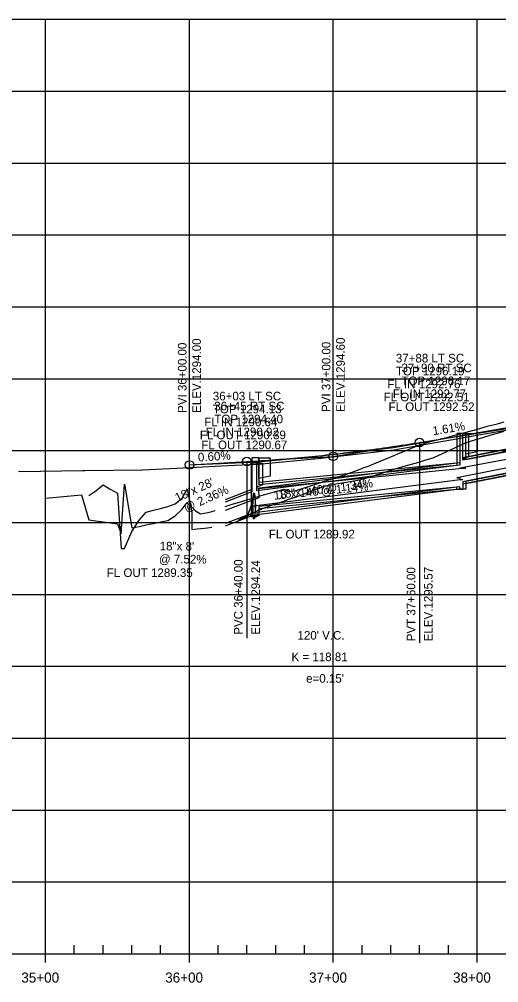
# Model space of a CAD drawing. Extents: x 670877 to 686811, y 705985 to 708501.
# Drawn here: x 684955 to 685288, y 707018 to 707688 of the extents above; entities that cross this region are included whole.
import ezdxf

# ---------------------------------------------------------------- set-up
doc = ezdxf.new("R2010")
doc.units = 0
for name, color, linetype in [('30', 7, 'Continuous'), ('37', 7, 'Continuous'), ('DRAINAGE_HGL LEFT', 7, 'Continuous'), ('DRAINAGE_HGL RIGHT', 7, 'Continuous'), ('Profile Drainage Annot Left', 7, 'Continuous'), ('Profile Drainage Annot Right', 7, 'Continuous'), ('R_Drainage Extensions_LEFT', 7, 'Continuous'), ('R_Drainage LEFT', 7, 'Continuous'), ('R_Drainage RIGHT', 7, 'Continuous'), ('R_Exist Surface', 7, 'Continuous'), ('R_Profile Work Left', 7, 'Continuous'), ('R_Profile Work Right', 7, 'Continuous'), ('R_Vert Alg', 7, 'Continuous'), ('R_Vert Alg Annot', 7, 'Continuous')]:
    doc.layers.add(name, color=color, linetype=linetype)

msp = doc.modelspace()

# ---------------------------------------------------------------- linework, layer by layer
at = {"layer": '37'}
for p, q in [((684473.03, 707688.43), (686573.03, 707688.43)), ((684973.03, 707038.43), (684973.03, 707688.43)), ((685073.03, 707038.43), (685073.03, 707688.43)), ((685173.03, 707038.43), (685173.03, 707688.43)), ((685273.03, 707038.43), (685273.03, 707688.43)), ((684473.03, 707638.43), (686573.03, 707638.43)), ((684473.03, 707588.43), (686573.03, 707588.43)), ((684473.03, 707538.43), (686573.03, 707538.43)), ((684473.03, 707488.43), (686573.03, 707488.43)), ((684473.03, 707438.43), (686573.03, 707438.43)), ((684473.03, 707388.43), (686573.03, 707388.43)), ((684473.03, 707338.43), (686573.03, 707338.43)), ((684473.03, 707288.43), (686573.03, 707288.43)), ((684473.03, 707238.43), (686573.03, 707238.43)), ((684473.03, 707188.43), (686573.03, 707188.43)), ((684473.03, 707138.43), (686573.03, 707138.43)), ((684473.03, 707088.43), (686573.03, 707088.43)), ((684993.03, 707038.43), (684993.03, 707044.43)), ((685013.03, 707038.43), (685013.03, 707044.43)), ((685033.03, 707038.43), (685033.03, 707044.43)), ((685053.03, 707038.43), (685053.03, 707044.43)), ((685093.03, 707038.43), (685093.03, 707044.43)), ((685113.03, 707038.43), (685113.03, 707044.43)), ((685133.03, 707038.43), (685133.03, 707044.43)), ((685153.03, 707038.43), (685153.03, 707044.43)), ((685193.03, 707038.43), (685193.03, 707044.43)), ((685213.03, 707038.43), (685213.03, 707044.43)), ((685233.03, 707038.43), (685233.03, 707044.43)), ((685253.03, 707038.43), (685253.03, 707044.43)), ((684473.03, 707038.43), (686573.03, 707038.43)), ((684973.03, 707032.43), (684973.03, 707038.43)), ((685073.03, 707032.43), (685073.03, 707038.43)), ((685173.03, 707032.43), (685173.03, 707038.43)), ((685273.03, 707032.43), (685273.03, 707038.43))]:
    msp.add_line(p, q, dxfattribs=at)
at = {"layer": 'DRAINAGE_HGL LEFT'}
for points in [[(685548.38, 707441), (685550.38, 707441), (685550.38, 707441), (685546.6, 707441), (685489.4, 707424), (685487.48, 707424), (685487.48, 707421.93), (685485.57, 707421.93), (685407.03, 707399.93), (685405.03, 707399.93), (685405.03, 707398.05), (685403.03, 707398.05), (685258.95, 707369.45), (685260.95, 707369.45), (685260.95, 707368.25), (685262.95, 707368.25), (685115.94, 707349.55), (685117.94, 707349.55)], [(685073.03, 707378.43), (685078.06, 707378.67), (685094.93, 707379.57), (685119.65, 707380.63), (685120.68, 707380.71), (685164.73, 707384.85), (685166.3, 707385.04), (685212.92, 707390.43), (685214.75, 707390.63), (685262.18, 707399.02), (685262.73, 707399.12), (685263.31, 707399.22), (685310, 707407.29)]]:
    msp.add_lwpolyline(points, dxfattribs=at)
at = {"layer": 'DRAINAGE_HGL RIGHT'}
msp.add_lwpolyline([(685545.7, 707448.17), (685547.73, 707448.17), (685547.73, 707448.17), (685547.73, 707448.17), (685489.71, 707427.57), (685487.73, 707427.57), (685487.73, 707427.18), (685485.75, 707427.18), (685403.03, 707404.88), (685405.03, 707404.88), (685405.03, 707403.45), (685407.03, 707403.45), (685261.02, 707376.21), (685263.02, 707376.21), (685263.02, 707376.21), (685265.02, 707376.21), (685120.97, 707361.92), (685121.24, 707355.66), (685097.92, 707346.66)], dxfattribs=at)
at = {"layer": 'R_Drainage Extensions_LEFT'}
for points in [[(685262.95, 707400.33), (685266.95, 707400.33), (685266.94, 707384.2), (685262.94, 707382.53), (685262.95, 707400.33)], [(685119.94, 707379.63), (685123.94, 707379.63), (685123.94, 707364.63), (685119.94, 707362.96), (685119.94, 707379.63)]]:
    msp.add_lwpolyline(points, dxfattribs=at)
at = {"layer": 'R_Drainage LEFT'}
for points in [[(685403.03, 707411.3), (685262.95, 707383.49)], [(685403.03, 707409.63), (685262.95, 707381.82)], [(685262.95, 707400.33), (685258.95, 707400.33)], [(685258.95, 707400.33), (685258.95, 707378.02)], [(685262.95, 707381.82), (685262.95, 707400.33)], [(685403.03, 707394.63), (685262.95, 707366.82)], [(685403.03, 707392.96), (685262.95, 707365.16)], [(685119.94, 707379.63), (685115.94, 707379.63)], [(685115.94, 707379.63), (685115.94, 707344.83)], [(685258.95, 707379.69), (685119.94, 707362)], [(685119.94, 707360.34), (685119.94, 707379.63)], [(685258.95, 707378.02), (685119.94, 707360.34)], [(685262.95, 707366.82), (685262.95, 707361.35)], [(685258.95, 707363.02), (685119.94, 707345.34)], [(685258.95, 707361.35), (685119.94, 707343.67)], [(685258.95, 707361.35), (685258.95, 707363.02)], [(685262.95, 707361.35), (685258.95, 707361.35)], [(685115.94, 707342.33), (685115.94, 707344.83)], [(685119.94, 707345.34), (685119.94, 707342.33)], [(685119.94, 707342.33), (685115.94, 707342.33)]]:
    msp.add_lwpolyline(points, dxfattribs=at)
for major_axis in [(0, 9.17), (0, 7.5)]:
    msp.add_ellipse((685117.94, 707349.83), major_axis=major_axis, ratio=0.1, dxfattribs=at)
at = {"layer": 'R_Drainage RIGHT'}
for points in [[(685403.03, 707410.32), (685265.02, 707383.57)], [(685403.03, 707408.65), (685265.02, 707381.9)], [(685265.02, 707400.33), (685261.02, 707400.33)], [(685261.02, 707400.33), (685261.02, 707378.24)], [(685265.02, 707381.9), (685265.02, 707400.33)], [(685265.02, 707400.33), (685273.02, 707400.33), (685273.02, 707387.58), (685265.02, 707385.91), (685265.02, 707400.33)], [(685403.03, 707393.65), (685265.02, 707366.9)], [(685403.03, 707391.99), (685265.02, 707365.24)], [(685121.24, 707383.43), (685116.36, 707383.43)], [(685116.36, 707383.43), (685116.36, 707359.75)], [(685121.24, 707383.43), (685129.24, 707383.43), (685129.24, 707370.68), (685121.24, 707369.01), (685121.24, 707383.43)], [(685121.24, 707383.43), (685121.24, 707364.56)], [(685261.02, 707379.9), (685121.24, 707366.23)], [(685261.02, 707378.24), (685121.24, 707364.56)], [(685265.02, 707366.9), (685265.02, 707361.57)], [(685116.36, 707361.41), (685097.92, 707354.3)], [(685116.36, 707359.75), (685097.92, 707352.63)], [(685261.02, 707363.24), (685121.24, 707349.56)], [(685261.02, 707361.57), (685121.24, 707347.9)], [(685261.02, 707361.57), (685261.02, 707363.24)], [(685265.02, 707361.57), (685261.02, 707361.57)], [(685116.36, 707344.75), (685097.92, 707337.63)], [(685116.36, 707343.08), (685116.36, 707344.75)], [(685121.24, 707349.56), (685121.24, 707343.08)], [(685116.36, 707343.08), (685097.92, 707335.96)], [(685121.24, 707343.08), (685116.36, 707343.08)]]:
    msp.add_lwpolyline(points, dxfattribs=at)
at = {"layer": 'R_Exist Surface'}
msp.add_lwpolyline([(684954.35, 707374.02), (684954.94, 707373.95), (684998.66, 707374.54), (685000.29, 707374.63), (685039.92, 707375.15), (685040.51, 707375.16), (685078.15, 707377), (685095.01, 707377.9), (685119.75, 707378.97), (685120.82, 707379.04), (685164.91, 707383.19), (685166.5, 707383.38), (685213.11, 707388.77), (685214.99, 707388.98), (685262.47, 707397.38), (685263.02, 707397.47), (685263.59, 707397.57), (685310.24, 707405.64)], dxfattribs=at)
at = {"layer": 'R_Profile Work Left'}
for points in [[(685116.64, 707352.01), (685113.34, 707343.47), (685107.04, 707339.8), (685112.07, 707342.39), (685117.1, 707344.98), (685121.37, 707347.17), (685122.13, 707347.52), (685127.15, 707349.3), (685132.17, 707351.07), (685137.18, 707352.85), (685137.98, 707353.13), (685142.2, 707354.62), (685147.22, 707356.39), (685152.24, 707358.21), (685157.26, 707360.11), (685162.28, 707362.02), (685166.24, 707363.52), (685167.29, 707363.9), (685172.3, 707364.78), (685177.3, 707365.67), (685182.31, 707366.55), (685187.31, 707367.44), (685192.32, 707368.32), (685192.45, 707368.34), (685197.33, 707369.74), (685202.34, 707371.38), (685207.35, 707373.02), (685212.36, 707374.66), (685215.32, 707375.63), (685217.38, 707376.22), (685222.39, 707377.65), (685227.39, 707379.08), (685232.4, 707380.5), (685237.41, 707381.93), (685242.42, 707383.46), (685247.28, 707385.71), (685247.44, 707385.78), (685252.46, 707388.11), (685257.48, 707390.43), (685259.9, 707391.55), (685260.34, 707391.76), (685260.49, 707391.83), (685261.5, 707392.29), (685262.06, 707392.55), (685263.03, 707393.01), (685263.34, 707393.16), (685267.03, 707394.56), (685272.03, 707396.06), (685273.03, 707396.37), (685277.03, 707397.57), (685282.03, 707399.08), (685282.8, 707399.31), (685287.03, 707400.58), (685291.86, 707402.03)], [(685003.03, 707357.29), (685008.03, 707360.5), (685013.03, 707364.55), (685018.03, 707361.63), (685023.03, 707358.72), (685025.66, 707320.34), (685028.03, 707320.26), (685033.03, 707332.25), (685038.03, 707339.97), (685043.03, 707345.64), (685048.03, 707346.91), (685053.03, 707348.19), (685058.03, 707349.46), (685063.03, 707351.5), (685068.03, 707355.42), (685071.39, 707361.51), (685074.64, 707345.44), (685074.7, 707333.56), (685078.39, 707333.96), (685083.46, 707334.52), (685085.51, 707334.74), (685088.53, 707335.07)]]:
    msp.add_lwpolyline(points, dxfattribs=at)
at = {"layer": 'R_Profile Work Right'}
for points in [[(685274.95, 707403.79), (685280.06, 707405.37), (685280.85, 707405.64), (685287.03, 707407.02)], [(685287.03, 707407.02), (685291.86, 707408.52)], [(685097.86, 707349.55), (685102.86, 707351.07), (685107.86, 707352.58), (685112.87, 707354.09), (685117.87, 707355.6), (685122.12, 707356.89), (685122.87, 707357.12), (685127.88, 707358.63), (685132.88, 707360.04), (685137.88, 707361.42), (685138.68, 707361.64), (685142.88, 707360.01), (685147.88, 707360.87), (685152.88, 707362.5), (685157.89, 707364.14), (685162.89, 707365.78), (685166.84, 707367.07), (685167.89, 707367.42), (685172.89, 707369.06), (685177.9, 707370.7), (685182.9, 707372.38), (685187.9, 707374.22), (685192.91, 707376.06), (685193.04, 707376.11), (685197.91, 707377.91), (685202.91, 707379.96), (685207.92, 707382.02), (685212.92, 707384.08), (685215.87, 707385.3), (685217.92, 707386.14), (685222.93, 707388.2), (685227.45, 707390.08), (685232.47, 707392.18), (685237.48, 707393.76), (685242.49, 707395.17), (685247.33, 707396.47), (685247.5, 707396.51), (685252.51, 707397.84), (685257.52, 707399.18), (685259.92, 707399.82), (685260.37, 707399.94), (685260.52, 707399.98), (685261.52, 707400.25), (685259.69, 707399.77), (685260.14, 707399.89), (685260.46, 707399.97), (685264.72, 707401.1), (685269.84, 707402.44), (685270.86, 707402.71), (685274.95, 707403.79)], [(684973.03, 707355.3), (684978.03, 707355.79), (684983.03, 707356.27), (684988.03, 707356.76), (684993.03, 707357.24), (684998.03, 707357.72), (685003.03, 707340.19), (685008.03, 707339.52), (685013.03, 707338.84), (685018.03, 707338.16), (685023.03, 707337.49), (685025.66, 707330.6), (685028.03, 707365.18), (685033.03, 707334.7), (685038.03, 707335.66), (685043.03, 707336.73), (685048.03, 707337.79), (685053.03, 707338.86), (685058.03, 707339.93), (685063.03, 707343.08), (685068.03, 707347.66), (685071.32, 707352.07), (685076.02, 707347.77), (685077.29, 707346.6), (685080.79, 707344.53), (685085.85, 707345.46), (685087.89, 707345.84), (685090.94, 707346.78)]]:
    msp.add_lwpolyline(points, dxfattribs=at)
at = {"layer": 'R_Vert Alg'}
for p, q in [((685233.03, 707394.1), (685298.03, 707404.57)), ((685143.03, 707382.63), (685173.03, 707384.43)), ((685173.03, 707384.43), (685203.03, 707389.26)), ((685073.03, 707378.43), (685113.03, 707380.83))]:
    msp.add_line(p, q, dxfattribs=at)
msp.add_lwpolyline([(685113.03, 707380.83), (685115.53, 707380.98), (685118.03, 707381.14), (685120.53, 707381.3), (685123.03, 707381.47), (685125.53, 707381.65), (685128.03, 707381.82), (685130.53, 707382.01), (685133.03, 707382.2), (685135.53, 707382.39), (685138.03, 707382.59), (685140.53, 707382.8), (685143.03, 707383.01), (685145.53, 707383.22), (685148.03, 707383.45), (685150.53, 707383.67), (685153.03, 707383.9), (685155.53, 707384.14), (685158.03, 707384.38), (685160.53, 707384.63), (685163.03, 707384.88), (685165.53, 707385.14), (685168.03, 707385.4), (685170.53, 707385.67), (685175.53, 707386.23), (685178.03, 707386.51), (685180.53, 707386.8), (685183.03, 707387.09), (685185.53, 707387.39), (685188.03, 707387.7), (685190.53, 707388.01), (685193.03, 707388.33), (685195.53, 707388.65), (685198.03, 707388.97), (685200.53, 707389.31), (685203.03, 707389.64), (685205.53, 707389.99), (685208.03, 707390.33), (685210.53, 707390.69), (685213.03, 707391.04), (685215.53, 707391.41), (685218.03, 707391.78), (685220.53, 707392.15), (685223.03, 707392.53), (685225.53, 707392.91), (685228.03, 707393.3), (685230.53, 707393.7), (685233.03, 707394.1)], dxfattribs=at)
for centre in [(685233.03, 707394.1), (685113.03, 707380.83), (685173.03, 707384.43), (685073.03, 707378.43)]:
    msp.add_circle(centre, 3, dxfattribs=at)
at = {"layer": 'R_Vert Alg Annot'}
for p, q in [((685073.03, 707378.43), (685073.03, 707489.68)), ((685173.03, 707384.43), (685173.03, 707490.3)), ((685233.03, 707394.1), (685233.03, 707254.82)), ((685113.03, 707380.83), (685113.03, 707258.01))]:
    msp.add_line(p, q, dxfattribs=at)

# ---------------------------------------------------------------- texts
at = {"layer": '30'}
for s, p in [('35+00', (684956.22, 707018.43)), ('36+00', (685056.22, 707018.43)), ('37+00', (685156.22, 707018.43)), ('38+00', (685256.22, 707018.43))]:
    msp.add_text(s, height=7, dxfattribs=at).set_placement(p)
at = {"layer": 'Profile Drainage Annot Left'}
for s, p in [('37+88 LT SC', (685216.49, 707449.74)), ('TOP 1296.19', (685216.51, 707440.74)), ('FL IN 1292.76', (685210.54, 707431.74)), ('36+03 LT SC', (685089.29, 707423.36)), ('FL OUT 1292.51', (685207.97, 707422.74)), ('TOP 1294.13', (685089.34, 707414.36)), ('FL IN 1290.64', (685083.34, 707405.36)), ('FL OUT 1290.39', (685080.31, 707396.36)), ('FL OUT 1289.35', (685015.59, 707300.52))]:
    msp.add_text(s, height=6, dxfattribs=at).set_placement(p)
for s, rotation, p in [('18"x 140\'@ 1.34%', 7.06177, (685135.26, 707354.9)), ('18"x 8\'', 359.61544, (685052.34, 707319.05)), ('@ 7.52%', 359.61544, (685051.83, 707310.05))]:
    msp.add_text(s, height=6, rotation=rotation, dxfattribs=at).set_placement(p)
at = {"layer": 'Profile Drainage Annot Right'}
for s, p in [('37+90 RT SC', (685220.37, 707442.95)), ('TOP 1296.17', (685220.4, 707433.95)), ('FL IN 1292.77', (685214.4, 707424.95)), ('36+45 RT SC', (685090.28, 707416.42)), ('FL OUT 1292.52', (685211.41, 707415.95)), ('TOP 1294.40', (685090.36, 707407.42)), ('FL IN 1290.92', (685084.32, 707398.42)), ('FL OUT 1290.67', (685081.31, 707389.42)), ('FL OUT 1289.92', (685128.22, 707327.34))]:
    msp.add_text(s, height=6, dxfattribs=at).set_placement(p)
for s, rotation, p in [('18"x 28\'', 24.22352, (685064.65, 707352.62)), ('@ 2.36%', 24.22352, (685070.67, 707345.46)), ('18"x 140\'@ 1.14%', 5.58741, (685131.93, 707354.24))]:
    msp.add_text(s, height=6, rotation=rotation, dxfattribs=at).set_placement(p)
at = {"layer": 'R_Vert Alg Annot'}
for s, rotation, p in [('ELEV.1294.00', 90, (685081.03, 707414.68)), ('ELEV.1294.60', 90, (685181.03, 707415.3)), ('PVI 36+00.00', 90, (685071.03, 707414.68)), ('PVI 37+00.00', 90, (685171.03, 707415.3)), ('1.61%', 9.15411, (685242.49, 707399.11)), ('0.60%', 3.43363, (685079.13, 707380.8)), ('PVC 36+40.00', 90, (685110.03, 707260.37)), ('ELEV.1294.24', 90, (685122.03, 707260.37)), ('PVT 37+60.00', 90, (685230.03, 707255.82)), ('ELEV.1295.57', 90, (685242.03, 707255.82))]:
    msp.add_text(s, height=6, rotation=rotation, dxfattribs=at).set_placement(p)
for s, p in [("120' V.C.", (685148.13, 707256.98)), ('K = 118.81', (685143.99, 707241.98)), ("e=0.15'", (685154.13, 707226.98))]:
    msp.add_text(s, height=6, dxfattribs=at).set_placement(p)

doc.saveas('drawing.dxf')
